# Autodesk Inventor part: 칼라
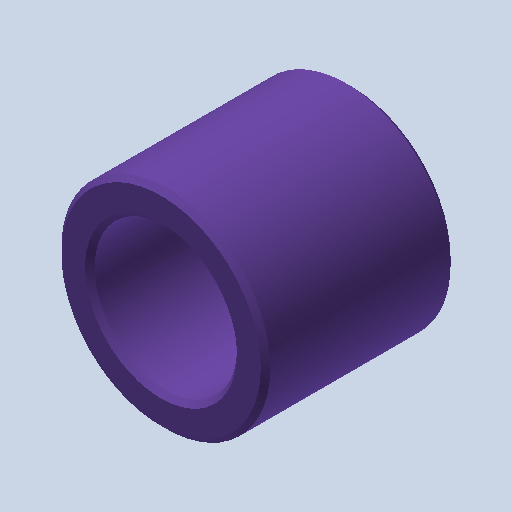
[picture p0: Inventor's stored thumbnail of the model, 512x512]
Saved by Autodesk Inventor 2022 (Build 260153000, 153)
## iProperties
Created: 2015-09
Part Number: 칼라
Document SubType Name: Modeling
Designer: mduedu
Density: 1 g/cm^3
Material: 스테인리스강
Appearance: 보라색
Author: mduedu
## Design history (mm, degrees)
node "작업 평면1"
node "작업 평면2"
sketch "스케치1"
  geometry: C1 r 7.5 at (0, 0); C2 r 11 at (0, 0); 1 further point
  constraints: 2 centre point, 2 coincident
  dimensions: "d0" = 15 diameter of C1; "d1" = 22 diameter of C2
extrude "돌출1" new body sketch "스케치1" distance "d2" = 20; taper "d3" = 0 deg
chamfer "모따기1" distance "d4" = 0.5; stored, may be unused: second distance "d5" = 2, angle "d6" = 45 deg
node "솔리드1"
